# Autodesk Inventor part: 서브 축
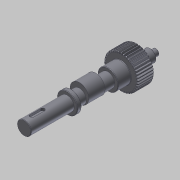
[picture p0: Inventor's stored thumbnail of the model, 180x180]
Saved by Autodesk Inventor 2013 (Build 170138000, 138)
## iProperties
Created: 2016-02
Part Number: 서브 축
Material: 강철, 연강
Document SubType Name: Modeling
Designer: mdu
Categories: <?xml version="1.0" encoding="UTF-16"?> <MemberInstance><Categories><FamilyTemplate><FamilyTemplateParameter ValueType="xs:double" Id="1" ObjectReferenceKey="da
Density: 7.86 g/cm^3
Mass: 504.229 g
Surface Area: 165.255 cm^2
Volume: 64.1513 cm^3
CustomPartVersion: 1
Author: mdu
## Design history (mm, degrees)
sketch "Sketch1"
  geometry: C1 r 21 at (0, 0)
  constraints: 1 centre point
  dimensions: "d0" = 42 diameter of C1 (= da_da)
extrude "Extrusion1" new body sketch "Sketch1" distance "d1" = 20 (= da_b); taper "d2" = 0 deg
workplane "Work Plane2"
feature "피치 지름" dims "d4" = 10, "d5" = 0
workplane "Work Plane8"
workplane "Work Plane9"
chamfer "모따기1" distance "d49" = 1; stored, may be unused: second distance "d50" = 2, angle "d51" = 45 deg
sketch "스케치3"
  geometry: C1 r 12.5 at (0, 0); 1 further point
  constraints: 1 centre point, 1 coincident
  dimensions: "d52" = 25 diameter of C1
extrude "돌출2" join sketch "스케치3" distance "d53" = 16; taper "d54" = 0 deg
sketch "스케치4"
  geometry: C1 r 8.5 at (0, 0); 1 further point
  constraints: 1 centre point, 1 coincident
  dimensions: "d55" = 17 diameter of C1
extrude "돌출3" join sketch "스케치4" distance "d56" = 103; taper "d57" = 0 deg
sketch "스케치5"
  geometry: C1 r 7.5 at (0, 0); 1 further point
  constraints: 1 centre point, 1 coincident
  dimensions: "d62" = 15 diameter of C1
extrude "돌출4" join sketch "스케치5" distance "d63" = 16; taper "d64" = 0 deg
sketch "스케치6"
  geometry: C1 r 4 at (0, 0); 1 further point
  constraints: 1 centre point, 1 coincident
  dimensions: "d65" = 8 diameter of C1
extrude "돌출5" join sketch "스케치6" distance "d66" = 7; taper "d67" = 0 deg
chamfer "모따기2" distance "d58" = 0.5; stored, may be unused: second distance "d59" = 2, angle "d60" = 45 deg
fillet "모깎기1" dims "d61" = 0.5
feature "스퍼 기어" dims "da_b" = 20, "da_d" = 40, "da_aw" = 31, "da_da" = 42, "da_df" = 37.5, "da_dw" = 40, angle "da_beta" = 0 deg, "da_lefttooth" = 0, "da_righttooth" = 0
node "작업 평면11"
sketch "스케치7"
  geometry: C1 r 8.5 at (0, 0) reference; C2 r 11.5 at (0, 3); 1 further point
  constraints: 1 centre point, 1 tangent, 1 vertical alignment
  dimensions: "d71" = 3 distance of C2.centre point (0, 0); "d72" = 23 diameter of C2 (derived)
extrude "돌출6" join sketch "스케치7" stored distance "d73" = 20; taper "d74" = 0 deg
node "작업 평면12"
sketch "스케치8"
  geometry: C1 r 12.5 at (0, 0) reference; 1 further point
extrude "돌출7" join sketch "스케치8" distance "d76" = 5; taper "d77" = 0 deg
chamfer "모따기3" distance "d78" = 0.5; stored, may be unused: second distance "d79" = 2, angle "d80" = 45 deg
sketch "스케치9"
  geometry: L1 (-8.5, 86)-(-8.5, 138.5) reference; L2 (-8, 139)-(8, 139) reference; L3 (0, 0)-(0, 139); L4 (-8.5, 115)-(0, 115); L5 (-8.5, 115)-(-8.5, 113.5); L6 (-7, 115)-(-8.5, 113.5)
  constraints: 8 end point, 4 point on line, 1 midpoint, 1 perpendicular
  dimensions: "d81" = 24 distance between parallel lines of L2 L4; "d82" = 45 deg angle of L6 L5; "d83" = 3 diameter of L5.end L4
revolve "회전1" sketch "스케치9" stored, may be unused: angle "d84" = 90 deg
sketch "스케치10"
  geometry: L1 (-8.5, 113.5)-(-7, 115) reference; L2 (-8.5, 116.5)-(-7, 115) reference; 2 further points
  constraints: 1 coincident
node "작업점1"
node "작업 평면14"
sketch "스케치11"
  geometry: L1 (8.5, 102.5)-(-8.5, 102.5) reference; L2 (0, 102.5)-(0, -36); L3 (-2.5, 93.5)-(-2.5, 80.5); L4 (2.5, 80.5)-(2.5, 93.5); L5 (-8, 103)-(8, 103) reference; A1 r 2.5 centre (0, 93.5) between (2.5, 93.5) and (-2.5, 93.5); A2 r 2.5 centre (0, 80.5) between (-2.5, 80.5) and (2.5, 80.5)
  constraints: 6 end point, 4 point on circle, 4 tangent, 2 centre point, 1 midpoint, 1 parallel, 1 perpendicular, 1 point on line, 1 vertical alignment
  dimensions: "d85" = 7 distance edge to line of A1 L5; "d86" = 18 dimension on A2 A1; "d87" = 5 distance between parallel lines of L3 L4
extrude "돌출8" cut sketch "스케치11" distance "d88" = 3; taper "d89" = 0 deg
body "Solid1"
sketch "Sketch2"
  geometry: C1 r 21 at (0, 0) reference; C2 r 20 at (0, 0)
  constraints: 1 centre point, 1 coincident
  dimensions: "d3" = 40 diameter of C2 (= da_dw)
body "Srf1"
other parameters: "d16" = 31 (= da_aw), "d17" = 0, "d34" = 4.5 deg (computed from da_z), "d39" = 0, "d41" = 0, "d43" = 31 (= da_aw), "d46" = 31 (= da_aw), "d47" = 0, "d48" = 0, "d68" = 25
